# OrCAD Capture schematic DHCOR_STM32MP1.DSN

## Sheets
1 DHCOR_with_NET_names: size A3; title: DHCOR STM32MP1; rev: R01
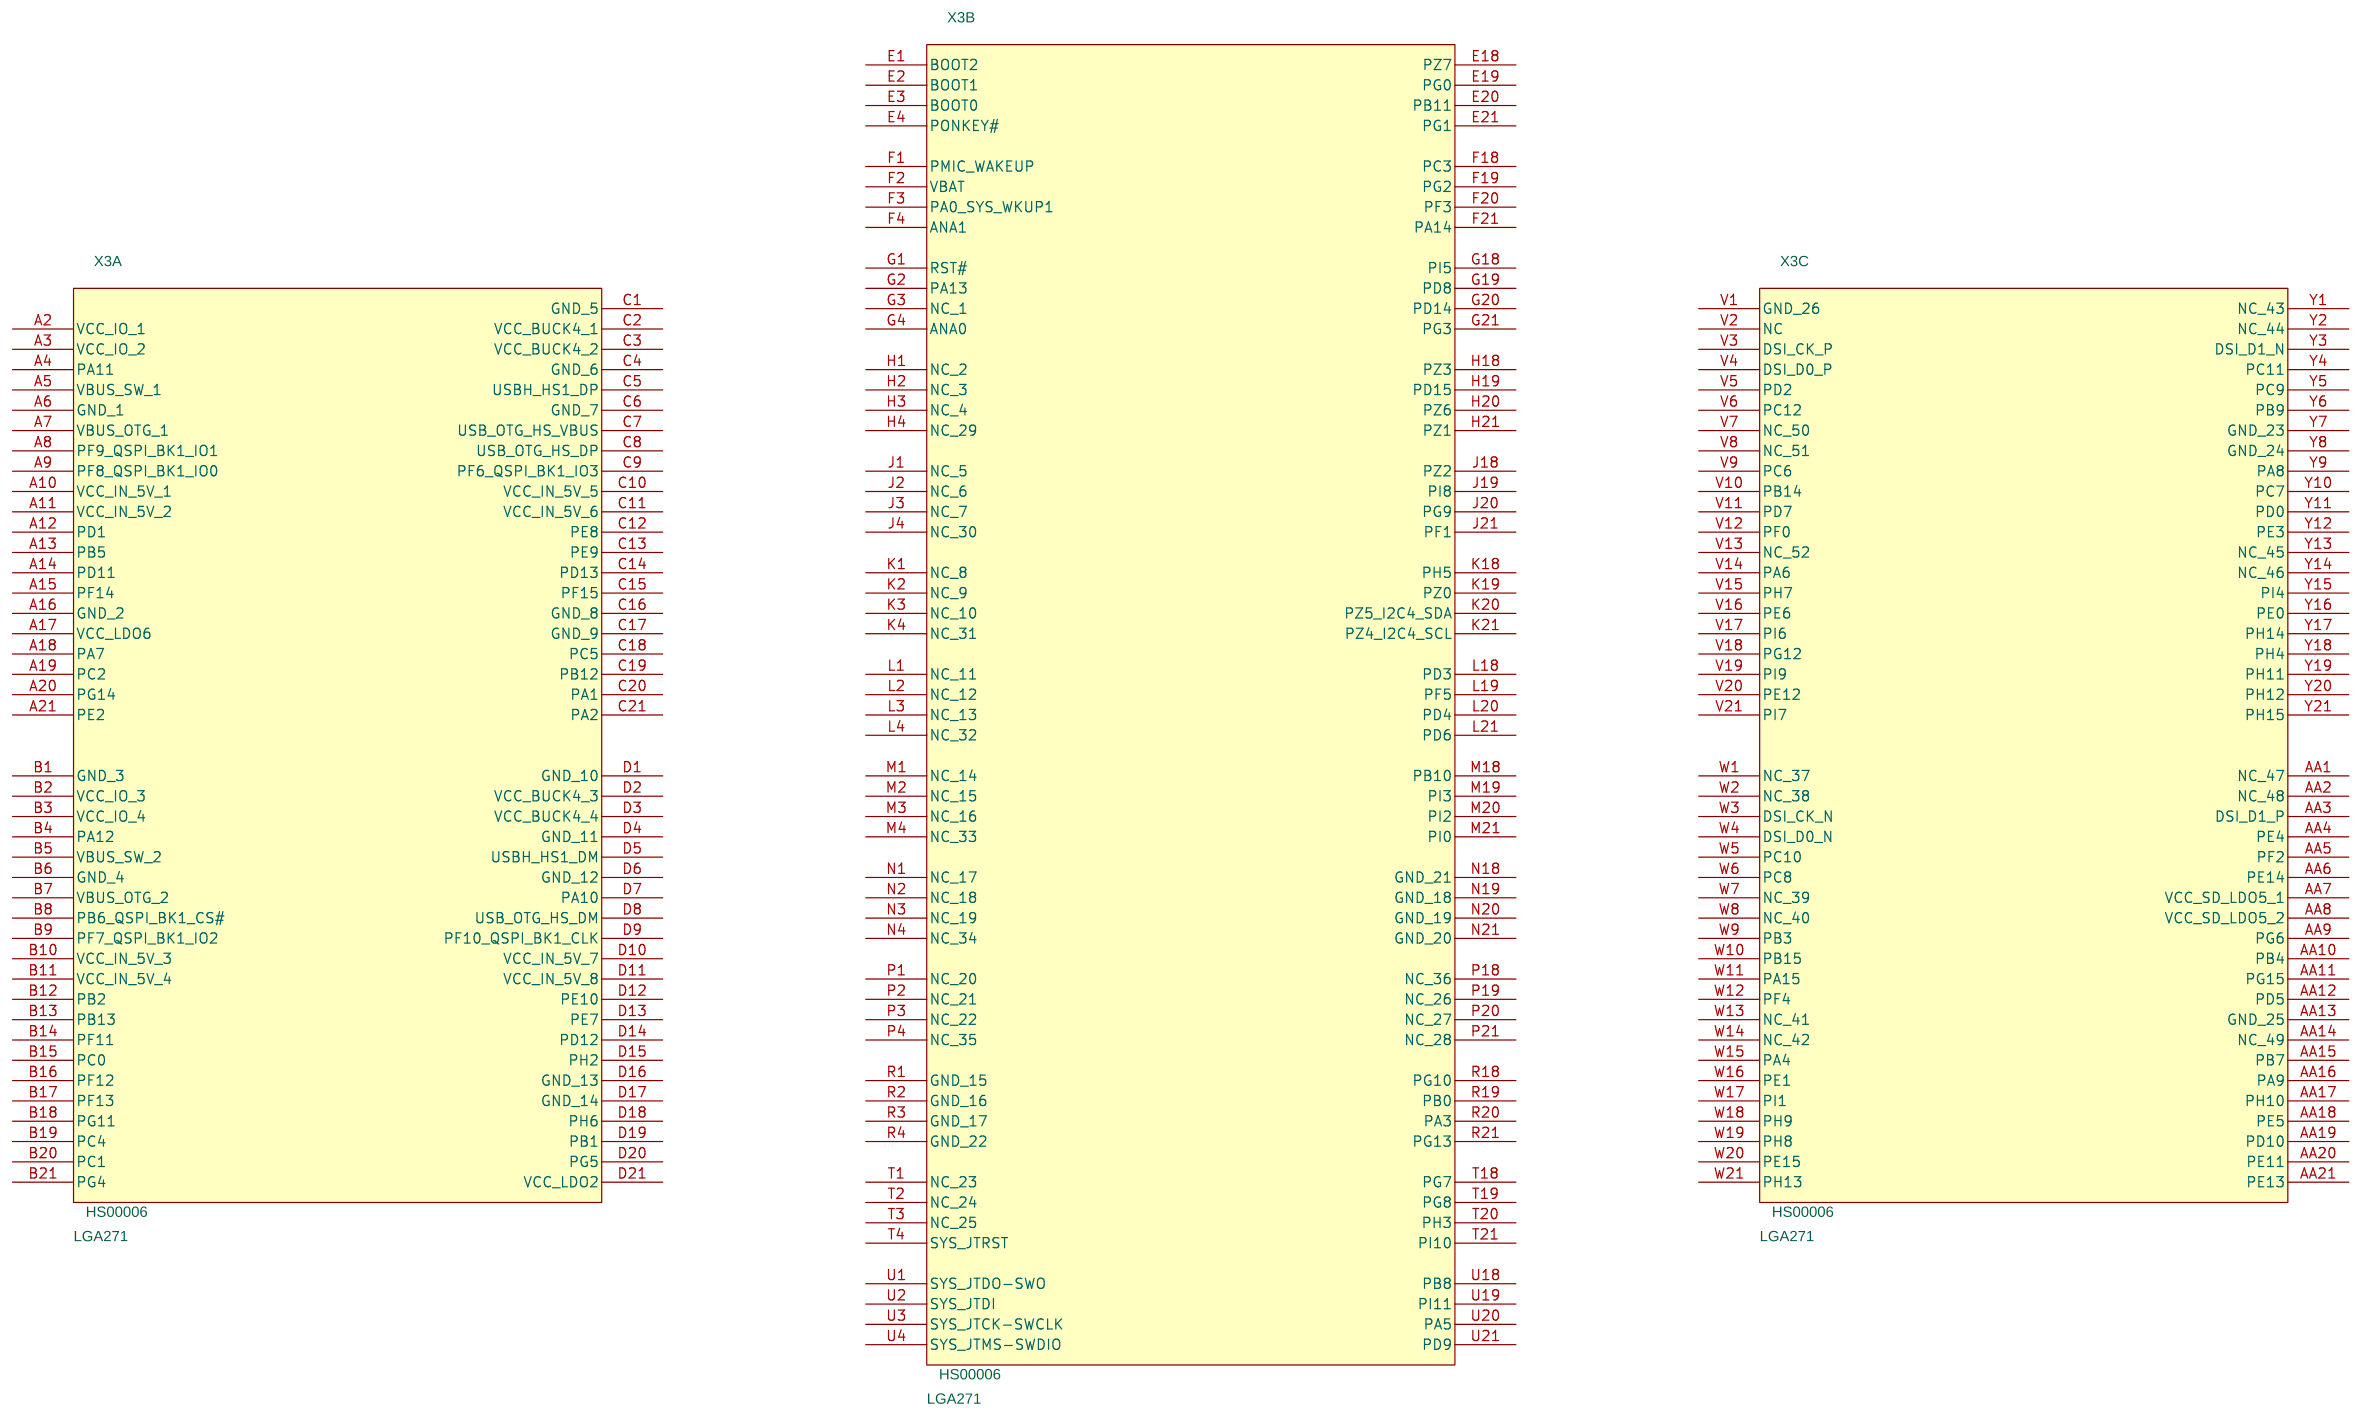
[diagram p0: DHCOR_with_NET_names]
2 DHCOR_without_NET_names: size A3
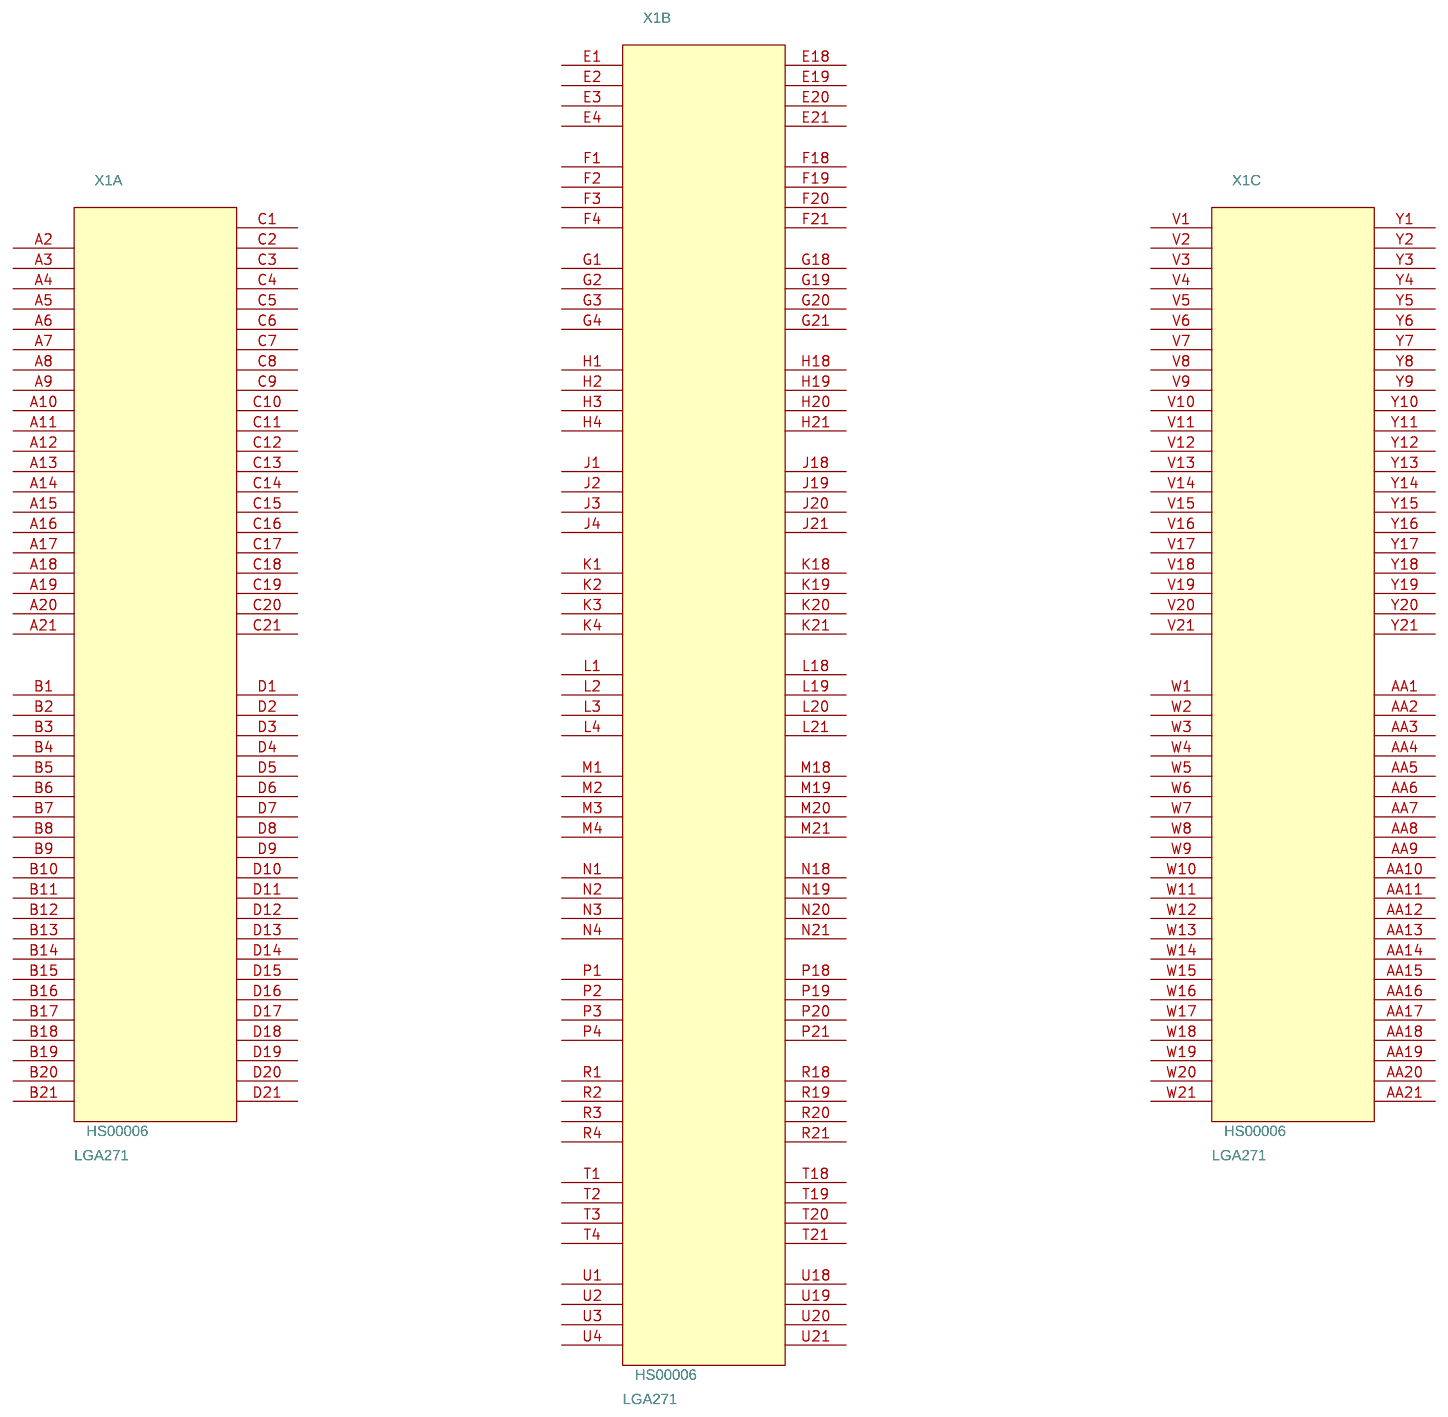
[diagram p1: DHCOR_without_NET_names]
3 DHCOR_Avenger96: size A3
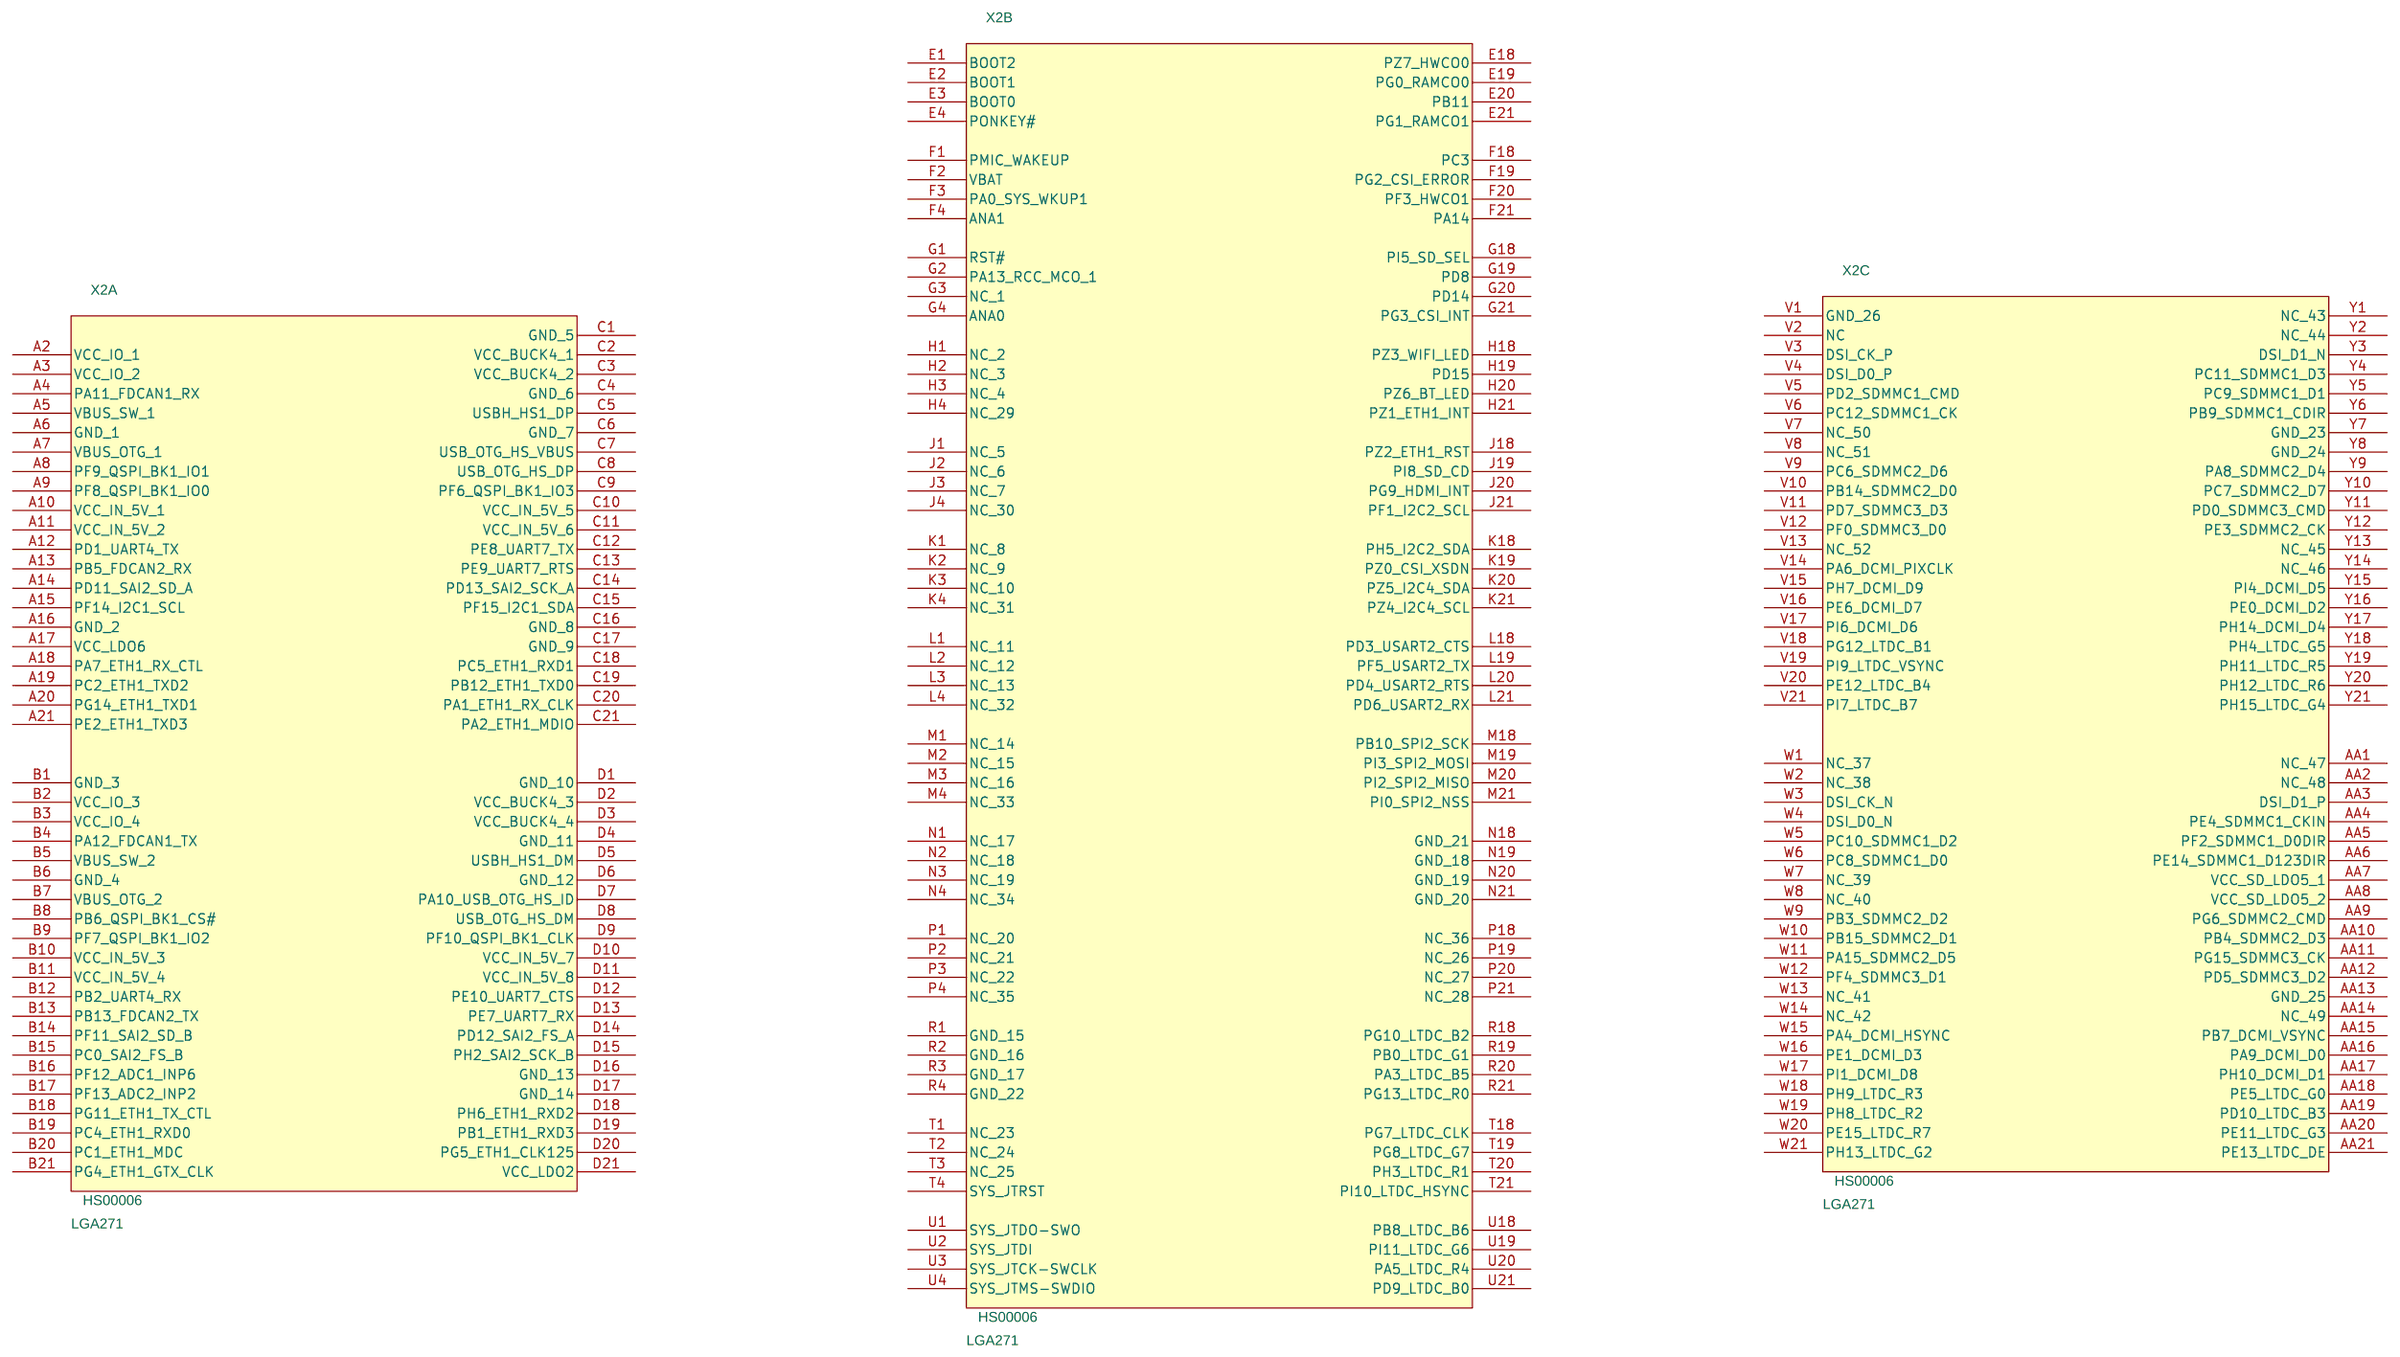
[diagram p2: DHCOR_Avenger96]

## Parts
sheet DHCOR_Avenger96
X2  HS00006  [LGA_1-27_29x29_271Pin_MB]  (sections A,B,C)
sheet DHCOR_with_NET_names
X3  HS00006  [LGA_1-27_29x29_271Pin_MB]  (sections A,B,C)
sheet DHCOR_without_NET_names
X1  HS00006  [LGA_1-27_29x29_271Pin_MB]  (sections A,B,C)

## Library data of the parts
X2 = DHCOR_STM32MP1_Avenger96: IC, DHCOR module DHCOR STM32MP15, LGA271, Ta=-40..85°C; Housing: LGA271; Manufacturer_Partnumber: DH #HS00006; Part_Number: IC-0620; Specified_Manufacturer: Yes; Temperature: -40°C to 85°C; Volt: 5V
X3 = DHCOR_STM32MP1_with_NET_names: IC, DHCOR module DHCOR STM32MP15, LGA271, Ta=-40..85°C; Housing: LGA271; Manufacturer_Partnumber: DH #HS00006; Part_Number: IC-0620; Specified_Manufacturer: Yes; Temperature: -40°C to 85°C; Volt: 5V
X1 = LGA_1-27_29x29_271P: IC, DHCOR module DHCOR STM32MP15, LGA271, Ta=-40..85°C; Housing: LGA271; Manufacturer_Partnumber: DH #HS00006; Part_Number: IC-0620; Specified_Manufacturer: Yes; Temperature: -40°C to 85°C; Volt: 5V

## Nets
GND_1: X2.A6(GND_1) X3.A6(GND_1)
GND_2: X2.A16(GND_2) X3.A16(GND_2)
GND_3: X2.B1(GND_3) X3.B1(GND_3)
GND_4: X2.B6(GND_4) X3.B6(GND_4)
GND_5: X2.C1(GND_5) X3.C1(GND_5)
GND_6: X2.C4(GND_6) X3.C4(GND_6)
GND_7: X2.C6(GND_7) X3.C6(GND_7)
GND_8: X2.C16(GND_8) X3.C16(GND_8)
GND_9: X2.C17(GND_9) X3.C17(GND_9)
GND_10: X2.D1(GND_10) X3.D1(GND_10)
GND_11: X2.D4(GND_11) X3.D4(GND_11)
GND_12: X2.D6(GND_12) X3.D6(GND_12)
GND_13: X2.D16(GND_13) X3.D16(GND_13)
GND_14: X2.D17(GND_14) X3.D17(GND_14)
GND_15: X2.R1(GND_15) X3.R1(GND_15)
GND_16: X2.R2(GND_16) X3.R2(GND_16)
GND_17: X2.R3(GND_17) X3.R3(GND_17)
GND_18: X2.N19(GND_18) X3.N19(GND_18)
GND_19: X2.N20(GND_19) X3.N20(GND_19)
GND_20: X2.N21(GND_20) X3.N21(GND_20)
GND_21: X2.N18(GND_21) X3.N18(GND_21)
GND_22: X2.R4(GND_22) X3.R4(GND_22)
GND_23: X2.Y7(GND_23) X3.Y7(GND_23)
GND_24: X2.Y8(GND_24) X3.Y8(GND_24)
GND_25: X2.AA13(GND_25) X3.AA13(GND_25)
GND_26: X2.V1(GND_26) X3.V1(GND_26)
VBAT: X2.F2(VBAT) X3.F2(VBAT)
VBUS_OTG_1: X2.A7(VBUS_OTG_1) X3.A7(VBUS_OTG_1)
VBUS_OTG_2: X2.B7(VBUS_OTG_2) X3.B7(VBUS_OTG_2)
VBUS_SW_1: X2.A5(VBUS_SW_1) X3.A5(VBUS_SW_1)
VBUS_SW_2: X2.B5(VBUS_SW_2) X3.B5(VBUS_SW_2)
VCC_BUCK4_1: X2.C2(VCC_BUCK4_1) X3.C2(VCC_BUCK4_1)
VCC_BUCK4_2: X2.C3(VCC_BUCK4_2) X3.C3(VCC_BUCK4_2)
VCC_BUCK4_3: X2.D2(VCC_BUCK4_3) X3.D2(VCC_BUCK4_3)
VCC_BUCK4_4: X2.D3(VCC_BUCK4_4) X3.D3(VCC_BUCK4_4)
VCC_IN_5V_1: X2.A10(VCC_IN_5V_1) X3.A10(VCC_IN_5V_1)
VCC_IN_5V_2: X2.A11(VCC_IN_5V_2) X3.A11(VCC_IN_5V_2)
VCC_IN_5V_3: X2.B10(VCC_IN_5V_3) X3.B10(VCC_IN_5V_3)
VCC_IN_5V_4: X2.B11(VCC_IN_5V_4) X3.B11(VCC_IN_5V_4)
VCC_IN_5V_5: X2.C10(VCC_IN_5V_5) X3.C10(VCC_IN_5V_5)
VCC_IN_5V_6: X2.C11(VCC_IN_5V_6) X3.C11(VCC_IN_5V_6)
VCC_IN_5V_7: X2.D10(VCC_IN_5V_7) X3.D10(VCC_IN_5V_7)
VCC_IN_5V_8: X2.D11(VCC_IN_5V_8) X3.D11(VCC_IN_5V_8)
VCC_IO_1: X2.A2(VCC_IO_1) X3.A2(VCC_IO_1)
VCC_IO_2: X2.A3(VCC_IO_2) X3.A3(VCC_IO_2)
VCC_IO_3: X2.B2(VCC_IO_3) X3.B2(VCC_IO_3)
VCC_IO_4: X2.B3(VCC_IO_4) X3.B3(VCC_IO_4)
VCC_LDO2: X2.D21(VCC_LDO2) X3.D21(VCC_LDO2)
VCC_LDO6: X2.A17(VCC_LDO6) X3.A17(VCC_LDO6)
VCC_SD_LDO5_1: X2.AA7(VCC_SD_LDO5_1) X3.AA7(VCC_SD_LDO5_1)
VCC_SD_LDO5_2: X2.AA8(VCC_SD_LDO5_2) X3.AA8(VCC_SD_LDO5_2)

Not connected (* = marked no-connect by the designer): X1 A2 A3 A4 A5 A6 A7 A8 A9 A10 A11 A12 A13 A14 A15 A16 A17 A18 A19 A20 A21 AA1 AA2 AA3 AA4 AA5 AA6 AA7 AA8 AA9 AA10 AA11 AA12 AA13 AA14 AA15 AA16 AA17 AA18 AA19 AA20 AA21 B1 B2 B3 B4 B5 B6 B7 B8 B9 B10 B11 B12 B13 B14 B15 B16 B17 B18 B19 B20 B21 C1 C2 C3 C4 C5 C6 C7 C8 C9 C10 C11 C12 C13 C14 C15 C16 C17 C18 C19 C20 C21 D1 D2 D3 D4 D5 D6 D7 D8 D9 D10 D11 D12 D13 D14 D15 D16 D17 D18 D19 D20 D21 E1 E2 E3 E4 E18 E19 E20 E21 F1 F2 F3 F4 F18 F19 F20 F21 G1 G2 G3 G4 G18 G19 G20 G21 H1 H2 H3 H4 H18 H19 H20 H21 J1 J2 J3 J4 J18 J19 J20 J21 K1 K2 K3 K4 K18 K19 K20 K21 L1 L2 L3 L4 L18 L19 L20 L21 M1 M2 M3 M4 M18 M19 M20 M21 N1 N2 N3 N4 N18 N19 N20 N21 P1 P2 P3 P4 P18 P19 P20 P21 R1 R2 R3 R4 R18 R19 R20 R21 T1 T2 T3 T4 T18 T19 T20 T21 U1 U2 U3 U4 U18 U19 U20 U21 V1 V2 V3 V4 V5 V6 V7 V8 V9 V10 V11 V12 V13 V14 V15 V16 V17 V18 V19 V20 V21 W1 W2 W3 W4 W5 W6 W7 W8 W9 W10 W11 W12 W13 W14 W15 W16 W17 W18 W19 W20 W21 Y1 Y2 Y3 Y4 Y5 Y6 Y7 Y8 Y9 Y10 Y11 Y12 Y13 Y14 Y15 Y16 Y17 Y18 Y19 Y20 Y21; X2 A4(PA11_FDCAN1_RX) A8(PF9_QSPI_BK1_IO1) A9(PF8_QSPI_BK1_IO0) A12(PD1_UART4_TX) A13(PB5_FDCAN2_RX) A14(PD11_SAI2_SD_A) A15(PF14_I2C1_SCL) A18(PA7_ETH1_RX_CTL) A19(PC2_ETH1_TXD2) A20(PG14_ETH1_TXD1) A21(PE2_ETH1_TXD3) AA1(NC_47) AA2(NC_48) AA3(DSI_D1_P) AA4(PE4_SDMMC1_CKIN) AA5(PF2_SDMMC1_D0DIR) AA6(PE14_SDMMC1_D123DIR) AA9(PG6_SDMMC2_CMD) AA10(PB4_SDMMC2_D3) AA11(PG15_SDMMC3_CK) AA12(PD5_SDMMC3_D2) AA14(NC_49) AA15(PB7_DCMI_VSYNC) AA16(PA9_DCMI_D0) AA17(PH10_DCMI_D1) AA18(PE5_LTDC_G0) AA19(PD10_LTDC_B3) AA20(PE11_LTDC_G3) AA21(PE13_LTDC_DE) B4(PA12_FDCAN1_TX) B8(PB6_QSPI_BK1_CS#) B9(PF7_QSPI_BK1_IO2) B12(PB2_UART4_RX) B13(PB13_FDCAN2_TX) B14(PF11_SAI2_SD_B) B15(PC0_SAI2_FS_B) B16(PF12_ADC1_INP6) B17(PF13_ADC2_INP2) B18(PG11_ETH1_TX_CTL) B19(PC4_ETH1_RXD0) B20(PC1_ETH1_MDC) B21(PG4_ETH1_GTX_CLK) C5(USBH_HS1_DP) C7(USB_OTG_HS_VBUS) C8(USB_OTG_HS_DP) C9(PF6_QSPI_BK1_IO3) C12(PE8_UART7_TX) C13(PE9_UART7_RTS) C14(PD13_SAI2_SCK_A) C15(PF15_I2C1_SDA) C18(PC5_ETH1_RXD1) C19(PB12_ETH1_TXD0) C20(PA1_ETH1_RX_CLK) C21(PA2_ETH1_MDIO) D5(USBH_HS1_DM) D7(PA10_USB_OTG_HS_ID) D8(USB_OTG_HS_DM) D9(PF10_QSPI_BK1_CLK) D12(PE10_UART7_CTS) D13(PE7_UART7_RX) D14(PD12_SAI2_FS_A) D15(PH2_SAI2_SCK_B) D18(PH6_ETH1_RXD2) D19(PB1_ETH1_RXD3) D20(PG5_ETH1_CLK125) E1(BOOT2) E2(BOOT1) E3(BOOT0) E4(PONKEY#) E18(PZ7_HWCO0) E19(PG0_RAMCO0) E20(PB11) E21(PG1_RAMCO1) F1(PMIC_WAKEUP) F3(PA0_SYS_WKUP1) F4(ANA1) F18(PC3) F19(PG2_CSI_ERROR) F20(PF3_HWCO1) F21(PA14) G1(RST#) G2(PA13_RCC_MCO_1) G3(NC_1) G4(ANA0) G18(PI5_SD_SEL) G19(PD8) G20(PD14) G21(PG3_CSI_INT) H1(NC_2) H2(NC_3) H3(NC_4) H4(NC_29) H18(PZ3_WIFI_LED) H19(PD15) H20(PZ6_BT_LED) H21(PZ1_ETH1_INT) J1(NC_5) J2(NC_6) J3(NC_7) J4(NC_30) J18(PZ2_ETH1_RST) J19(PI8_SD_CD) J20(PG9_HDMI_INT) J21(PF1_I2C2_SCL) K1(NC_8) K2(NC_9) K3(NC_10) K4(NC_31) K18(PH5_I2C2_SDA) K19(PZ0_CSI_XSDN) K20(PZ5_I2C4_SDA) K21(PZ4_I2C4_SCL) L1(NC_11) L2(NC_12) L3(NC_13) L4(NC_32) L18(PD3_USART2_CTS) L19(PF5_USART2_TX) L20(PD4_USART2_RTS) L21(PD6_USART2_RX) M1(NC_14) M2(NC_15) M3(NC_16) M4(NC_33) M18(PB10_SPI2_SCK) M19(PI3_SPI2_MOSI) M20(PI2_SPI2_MISO) M21(PI0_SPI2_NSS) N1(NC_17) N2(NC_18) N3(NC_19) N4(NC_34) P1(NC_20) P2(NC_21) P3(NC_22) P4(NC_35) P18(NC_36) P19(NC_26) P20(NC_27) P21(NC_28) R18(PG10_LTDC_B2) R19(PB0_LTDC_G1) R20(PA3_LTDC_B5) R21(PG13_LTDC_R0) T1(NC_23) T2(NC_24) T3(NC_25) T4(SYS_JTRST) T18(PG7_LTDC_CLK) T19(PG8_LTDC_G7) T20(PH3_LTDC_R1) T21(PI10_LTDC_HSYNC) U1(SYS_JTDO-SWO) U2(SYS_JTDI) U3(SYS_JTCK-SWCLK) U4(SYS_JTMS-SWDIO) U18(PB8_LTDC_B6) U19(PI11_LTDC_G6) U20(PA5_LTDC_R4) U21(PD9_LTDC_B0) V2(NC) V3(DSI_CK_P) V4(DSI_D0_P) V5(PD2_SDMMC1_CMD) V6(PC12_SDMMC1_CK) V7(NC_50) V8(NC_51) V9(PC6_SDMMC2_D6) V10(PB14_SDMMC2_D0) V11(PD7_SDMMC3_D3) V12(PF0_SDMMC3_D0) V13(NC_52) V14(PA6_DCMI_PIXCLK) V15(PH7_DCMI_D9) V16(PE6_DCMI_D7) V17(PI6_DCMI_D6) V18(PG12_LTDC_B1) V19(PI9_LTDC_VSYNC) V20(PE12_LTDC_B4) V21(PI7_LTDC_B7) W1(NC_37) W2(NC_38) W3(DSI_CK_N) W4(DSI_D0_N) W5(PC10_SDMMC1_D2) W6(PC8_SDMMC1_D0) W7(NC_39) W8(NC_40) W9(PB3_SDMMC2_D2) W10(PB15_SDMMC2_D1) W11(PA15_SDMMC2_D5) W12(PF4_SDMMC3_D1) W13(NC_41) W14(NC_42) W15(PA4_DCMI_HSYNC) W16(PE1_DCMI_D3) W17(PI1_DCMI_D8) W18(PH9_LTDC_R3) W19(PH8_LTDC_R2) W20(PE15_LTDC_R7) W21(PH13_LTDC_G2) Y1(NC_43) Y2(NC_44) Y3(DSI_D1_N) Y4(PC11_SDMMC1_D3) Y5(PC9_SDMMC1_D1) Y6(PB9_SDMMC1_CDIR) Y9(PA8_SDMMC2_D4) Y10(PC7_SDMMC2_D7) Y11(PD0_SDMMC3_CMD) Y12(PE3_SDMMC2_CK) Y13(NC_45) Y14(NC_46) Y15(PI4_DCMI_D5) Y16(PE0_DCMI_D2) Y17(PH14_DCMI_D4) Y18(PH4_LTDC_G5) Y19(PH11_LTDC_R5) Y20(PH12_LTDC_R6) Y21(PH15_LTDC_G4); X3 A4(PA11) A8(PF9_QSPI_BK1_IO1) A9(PF8_QSPI_BK1_IO0) A12(PD1) A13(PB5) A14(PD11) A15(PF14) A18(PA7) A19(PC2) A20(PG14) A21(PE2) AA1(NC_47) AA2(NC_48) AA3(DSI_D1_P) AA4(PE4) AA5(PF2) AA6(PE14) AA9(PG6) AA10(PB4) AA11(PG15) AA12(PD5) AA14(NC_49) AA15(PB7) AA16(PA9) AA17(PH10) AA18(PE5) AA19(PD10) AA20(PE11) AA21(PE13) B4(PA12) B8(PB6_QSPI_BK1_CS#) B9(PF7_QSPI_BK1_IO2) B12(PB2) B13(PB13) B14(PF11) B15(PC0) B16(PF12) B17(PF13) B18(PG11) B19(PC4) B20(PC1) B21(PG4) C5(USBH_HS1_DP) C7(USB_OTG_HS_VBUS) C8(USB_OTG_HS_DP) C9(PF6_QSPI_BK1_IO3) C12(PE8) C13(PE9) C14(PD13) C15(PF15) C18(PC5) C19(PB12) C20(PA1) C21(PA2) D5(USBH_HS1_DM) D7(PA10) D8(USB_OTG_HS_DM) D9(PF10_QSPI_BK1_CLK) D12(PE10) D13(PE7) D14(PD12) D15(PH2) D18(PH6) D19(PB1) D20(PG5) E1(BOOT2) E2(BOOT1) E3(BOOT0) E4(PONKEY#) E18(PZ7) E19(PG0) E20(PB11) E21(PG1) F1(PMIC_WAKEUP) F3(PA0_SYS_WKUP1) F4(ANA1) F18(PC3) F19(PG2) F20(PF3) F21(PA14) G1(RST#) G2(PA13) G3(NC_1) G4(ANA0) G18(PI5) G19(PD8) G20(PD14) G21(PG3) H1(NC_2) H2(NC_3) H3(NC_4) H4(NC_29) H18(PZ3) H19(PD15) H20(PZ6) H21(PZ1) J1(NC_5) J2(NC_6) J3(NC_7) J4(NC_30) J18(PZ2) J19(PI8) J20(PG9) J21(PF1) K1(NC_8) K2(NC_9) K3(NC_10) K4(NC_31) K18(PH5) K19(PZ0) K20(PZ5_I2C4_SDA) K21(PZ4_I2C4_SCL) L1(NC_11) L2(NC_12) L3(NC_13) L4(NC_32) L18(PD3) L19(PF5) L20(PD4) L21(PD6) M1(NC_14) M2(NC_15) M3(NC_16) M4(NC_33) M18(PB10) M19(PI3) M20(PI2) M21(PI0) N1(NC_17) N2(NC_18) N3(NC_19) N4(NC_34) P1(NC_20) P2(NC_21) P3(NC_22) P4(NC_35) P18(NC_36) P19(NC_26) P20(NC_27) P21(NC_28) R18(PG10) R19(PB0) R20(PA3) R21(PG13) T1(NC_23) T2(NC_24) T3(NC_25) T4(SYS_JTRST) T18(PG7) T19(PG8) T20(PH3) T21(PI10) U1(SYS_JTDO-SWO) U2(SYS_JTDI) U3(SYS_JTCK-SWCLK) U4(SYS_JTMS-SWDIO) U18(PB8) U19(PI11) U20(PA5) U21(PD9) V2(NC) V3(DSI_CK_P) V4(DSI_D0_P) V5(PD2) V6(PC12) V7(NC_50) V8(NC_51) V9(PC6) V10(PB14) V11(PD7) V12(PF0) V13(NC_52) V14(PA6) V15(PH7) V16(PE6) V17(PI6) V18(PG12) V19(PI9) V20(PE12) V21(PI7) W1(NC_37) W2(NC_38) W3(DSI_CK_N) W4(DSI_D0_N) W5(PC10) W6(PC8) W7(NC_39) W8(NC_40) W9(PB3) W10(PB15) W11(PA15) W12(PF4) W13(NC_41) W14(NC_42) W15(PA4) W16(PE1) W17(PI1) W18(PH9) W19(PH8) W20(PE15) W21(PH13) Y1(NC_43) Y2(NC_44) Y3(DSI_D1_N) Y4(PC11) Y5(PC9) Y6(PB9) Y9(PA8) Y10(PC7) Y11(PD0) Y12(PE3) Y13(NC_45) Y14(NC_46) Y15(PI4) Y16(PE0) Y17(PH14) Y18(PH4) Y19(PH11) Y20(PH12) Y21(PH15)
